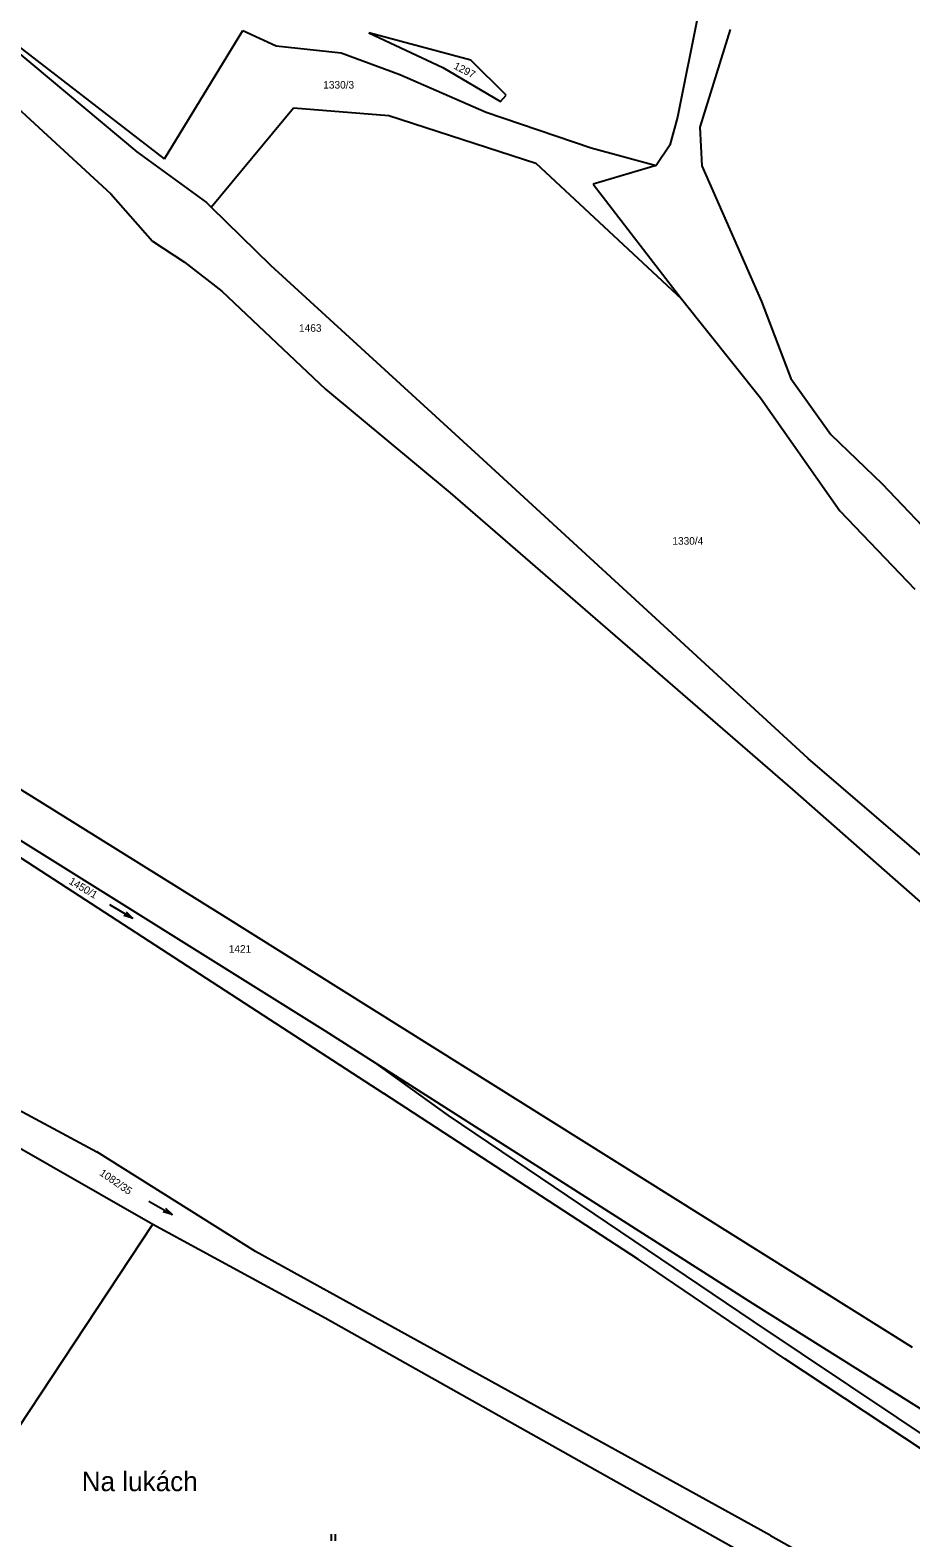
# Model space of a CAD drawing. Extents: x -852001 to -842497, y -1063614 to -1052182.
# Drawn here: x -849610.9 to -849412.3, y -1056094.9 to -1055755 of the extents above; entities that cross this region are included whole.
import ezdxf

# ---------------------------------------------------------------- set-up
doc = ezdxf.new("R2010")
doc.units = 0
for name, color, linetype in [('Default', 7, 'Continuous'), ('KN_HRANICE', 7, 'Continuous'), ('KN_KULTURY', 7, 'Continuous'), ('KN_PARCELY', 7, 'Continuous')]:
    doc.layers.add(name, color=color, linetype=linetype)

# ---------------------------------------------------------------- blocks, each defined once
blk = doc.blocks.new('306')
at = {"layer": 'Default'}
for p, q in [((-0.5, 1.5), (-0.5, 0)), ((0.5, 0), (0.5, 1.5))]:
    blk.add_line(p, q, dxfattribs=at)
blk = doc.blocks.new('802')
at = {"layer": 'Default'}
blk.add_line((-3, 0), (3, 0), dxfattribs=at)
blk.add_lwpolyline([(1, 0.5), (3, 0), (1, -0.5)], dxfattribs=at)

msp = doc.modelspace()

# ---------------------------------------------------------------- linework, layer by layer
at = {"layer": 'KN_HRANICE'}
for p, q in [((-849648.98, -1055740.17), (-849592.74, -1055791.88)), ((-849648.98, -1055740.17), (-849592.74, -1055791.88)), ((-849580.61, -1055784.02), (-849638.69, -1055739.15)), ((-849638.69, -1055739.15), (-849586.87, -1055782.4)), ((-849580.61, -1055784.02), (-849638.69, -1055739.15)), ((-849638.69, -1055739.15), (-849586.87, -1055782.4)), ((-849460.21, -1055751.02), (-849464.92, -1055774.59)), ((-849460.21, -1055751.02), (-849464.92, -1055774.59)), ((-849580.61, -1055784.02), (-849562.93, -1055755.11)), ((-849580.61, -1055784.02), (-849562.93, -1055755.11)), ((-849562.93, -1055755.11), (-849555.45, -1055758.51)), ((-849562.93, -1055755.11), (-849555.45, -1055758.51)), ((-849534.51, -1055755.58), (-849517.87, -1055763.4)), ((-849511.56, -1055761.79), (-849534.51, -1055755.58)), ((-849534.51, -1055755.58), (-849517.87, -1055763.4)), ((-849511.56, -1055761.79), (-849534.51, -1055755.58)), ((-849453.07, -1055754.88), (-849459.95, -1055776.85)), ((-849453.07, -1055754.88), (-849459.95, -1055776.85)), ((-849555.45, -1055758.51), (-849540.76, -1055760.08)), ((-849555.45, -1055758.51), (-849540.76, -1055760.08)), ((-849540.76, -1055760.08), (-849527.52, -1055764.96)), ((-849540.76, -1055760.08), (-849527.52, -1055764.96)), ((-849517.87, -1055763.4), (-849504.83, -1055771.1)), ((-849517.87, -1055763.4), (-849504.83, -1055771.1)), ((-849503.58, -1055769.69), (-849511.56, -1055761.79)), ((-849503.58, -1055769.69), (-849511.56, -1055761.79)), ((-849527.52, -1055764.96), (-849508.07, -1055773.48)), ((-849527.52, -1055764.96), (-849508.07, -1055773.48)), ((-849504.83, -1055771.1), (-849503.58, -1055769.69)), ((-849504.83, -1055771.1), (-849503.58, -1055769.69)), ((-849570.07, -1055794.9), (-849551.55, -1055772.52)), ((-849570.07, -1055794.9), (-849551.55, -1055772.52)), ((-849551.55, -1055772.52), (-849530, -1055774.25)), ((-849551.55, -1055772.52), (-849530, -1055774.25)), ((-849530, -1055774.25), (-849496.9, -1055784.95)), ((-849530, -1055774.25), (-849496.9, -1055784.95)), ((-849508.07, -1055773.48), (-849484.38, -1055781.49)), ((-849508.07, -1055773.48), (-849484.38, -1055781.49)), ((-849464.92, -1055774.59), (-849466.71, -1055780.89)), ((-849464.92, -1055774.59), (-849466.71, -1055780.89)), ((-849459.95, -1055776.85), (-849459.46, -1055785.61)), ((-849459.95, -1055776.85), (-849459.46, -1055785.61)), ((-849484.38, -1055781.49), (-849469.74, -1055785.5)), ((-849484.38, -1055781.49), (-849469.74, -1055785.5)), ((-849466.71, -1055780.89), (-849469.74, -1055785.5)), ((-849466.71, -1055780.89), (-849469.74, -1055785.5)), ((-849586.87, -1055782.4), (-849571.11, -1055793.89)), ((-849586.87, -1055782.4), (-849571.11, -1055793.89)), ((-849496.9, -1055784.95), (-849464.02, -1055815.6)), ((-849496.9, -1055784.95), (-849464.02, -1055815.6)), ((-849469.74, -1055785.5), (-849483.95, -1055789.72)), ((-849469.74, -1055785.5), (-849483.95, -1055789.72)), ((-849459.46, -1055785.61), (-849445.98, -1055816.21)), ((-849459.46, -1055785.61), (-849445.98, -1055816.21)), ((-849592.74, -1055791.88), (-849583.31, -1055802.6)), ((-849592.74, -1055791.88), (-849583.31, -1055802.6)), ((-849483.95, -1055789.72), (-849464.02, -1055815.6)), ((-849483.95, -1055789.72), (-849464.02, -1055815.6)), ((-849571.11, -1055793.89), (-849570.07, -1055794.9)), ((-849571.11, -1055793.89), (-849570.07, -1055794.9)), ((-849570.07, -1055794.9), (-849556.69, -1055807.96)), ((-849570.07, -1055794.9), (-849556.69, -1055807.96)), ((-849583.31, -1055802.6), (-849576.09, -1055807.27)), ((-849583.31, -1055802.6), (-849576.09, -1055807.27)), ((-849576.09, -1055807.27), (-849567.69, -1055813.82)), ((-849576.09, -1055807.27), (-849567.69, -1055813.82)), ((-849556.69, -1055807.96), (-849510.63, -1055850.15)), ((-849556.69, -1055807.96), (-849510.63, -1055850.15)), ((-849567.69, -1055813.82), (-849544.29, -1055835.94)), ((-849567.69, -1055813.82), (-849544.29, -1055835.94)), ((-849464.02, -1055815.6), (-849446.27, -1055837.88)), ((-849464.02, -1055815.6), (-849446.27, -1055837.88)), ((-849445.98, -1055816.21), (-849439.41, -1055833.57)), ((-849445.98, -1055816.21), (-849439.41, -1055833.57)), ((-849544.29, -1055835.94), (-849516.22, -1055859.35)), ((-849544.29, -1055835.94), (-849516.22, -1055859.35)), ((-849439.41, -1055833.57), (-849430.4, -1055846.13)), ((-849439.41, -1055833.57), (-849430.4, -1055846.13)), ((-849446.27, -1055837.88), (-849428.32, -1055863.36)), ((-849446.27, -1055837.88), (-849428.32, -1055863.36)), ((-849430.4, -1055846.13), (-849418.81, -1055857.28)), ((-849430.4, -1055846.13), (-849418.81, -1055857.28)), ((-849435.47, -1055919.24), (-849510.63, -1055850.15)), ((-849435.47, -1055919.24), (-849510.63, -1055850.15)), ((-849723.4, -1055857.46), (-849567.55, -1055954.51)), ((-849723.4, -1055857.46), (-849567.55, -1055954.51)), ((-849516.22, -1055859.35), (-849439.03, -1055926.18)), ((-849516.22, -1055859.35), (-849439.03, -1055926.18)), ((-849418.81, -1055857.28), (-849405.22, -1055871.56)), ((-849418.81, -1055857.28), (-849405.22, -1055871.56)), ((-849428.32, -1055863.36), (-849411.46, -1055881.02)), ((-849428.32, -1055863.36), (-849411.46, -1055881.02)), ((-849670.35, -1055901.85), (-849544.39, -1055980.59)), ((-849670.35, -1055901.85), (-849544.39, -1055980.59)), ((-849412.64, -1055938.82), (-849435.47, -1055919.24)), ((-849412.64, -1055938.82), (-849435.47, -1055919.24)), ((-849439.03, -1055926.18), (-849377.32, -1055980.55)), ((-849439.03, -1055926.18), (-849377.32, -1055980.55)), ((-849625.96, -1055933.24), (-849531.18, -1055994.73)), ((-849625.96, -1055933.24), (-849531.18, -1055994.73)), ((-849372.97, -1055973.13), (-849412.64, -1055938.82)), ((-849372.97, -1055973.13), (-849412.64, -1055938.82)), ((-849567.55, -1055954.51), (-849412.04, -1056051.96)), ((-849567.55, -1055954.51), (-849412.04, -1056051.96)), ((-849544.39, -1055980.59), (-849533.77, -1055987.36)), ((-849544.39, -1055980.59), (-849533.77, -1055987.36)), ((-849642.19, -1055983.02), (-849595.86, -1056007.92)), ((-849642.19, -1055983.02), (-849595.86, -1056007.92)), ((-849645.25, -1055988.73), (-849583.23, -1056024.23)), ((-849645.25, -1055988.73), (-849583.23, -1056024.23)), ((-849533.77, -1055987.36), (-849447.97, -1056042.09)), ((-849533.77, -1055987.36), (-849516.66, -1055999.69)), ((-849533.77, -1055987.36), (-849447.97, -1056042.09)), ((-849533.77, -1055987.36), (-849516.66, -1055999.69)), ((-849473.77, -1056032.19), (-849531.18, -1055994.73)), ((-849473.77, -1056032.19), (-849531.18, -1055994.73)), ((-849516.66, -1055999.69), (-849447.99, -1056046.05)), ((-849516.66, -1055999.69), (-849447.99, -1056046.05)), ((-849560.1, -1056030.34), (-849595.86, -1056007.92)), ((-849560.1, -1056030.34), (-849595.86, -1056007.92)), ((-849629.86, -1056094.78), (-849583.23, -1056024.23)), ((-849629.86, -1056094.78), (-849583.23, -1056024.23)), ((-849583.23, -1056024.23), (-849544.37, -1056045.31)), ((-849583.23, -1056024.23), (-849544.37, -1056045.31)), ((-849443.99, -1056094.41), (-849560.1, -1056030.34)), ((-849443.99, -1056094.41), (-849560.1, -1056030.34)), ((-849440.78, -1056054.56), (-849473.77, -1056032.19)), ((-849440.78, -1056054.56), (-849473.77, -1056032.19)), ((-849447.97, -1056042.09), (-849309.42, -1056129.11)), ((-849447.97, -1056042.09), (-849309.42, -1056129.11)), ((-849544.37, -1056045.31), (-849445.63, -1056100.85)), ((-849544.37, -1056045.31), (-849445.63, -1056100.85)), ((-849447.99, -1056046.05), (-849400.8, -1056077.65)), ((-849447.99, -1056046.05), (-849400.8, -1056077.65)), ((-849379.78, -1056094.91), (-849440.78, -1056054.56)), ((-849379.78, -1056094.91), (-849440.78, -1056054.56)), ((-849443.99, -1056094.41), (-849418.2, -1056108.82)), ((-849443.99, -1056094.41), (-849418.2, -1056108.82))]:
    msp.add_line(p, q, dxfattribs=at)

# ---------------------------------------------------------------- block references
at = {"layer": 'KN_KULTURY'}
for p, rotation in [((-849590.4, -1055953.67), -30.434675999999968), ((-849590.4, -1055953.67), -30.434675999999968), ((-849581.52, -1056020.52), -29.346056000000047), ((-849581.52, -1056020.52), -29.346056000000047)]:
    msp.add_blockref('802', p, dxfattribs=dict(at, rotation=rotation))
msp.add_blockref('306', (-849542.54, -1056095.59), dxfattribs=at)
msp.add_blockref('306', (-849542.54, -1056095.59), dxfattribs=at)

# ---------------------------------------------------------------- texts
at = {"layer": 'KN_PARCELY'}
for s, rotation, p in [('1297', 332.888, (-849515.57, -1055763.61)), ('1297', 332.888, (-849515.57, -1055763.61)), ('1450/1', 329.508, (-849602.34, -1055947.35)), ('1450/1', 329.508, (-849602.34, -1055947.35)), ('1082/35', 325.44, (-849595.41, -1056013.02)), ('1082/35', 325.44, (-849595.41, -1056013.02))]:
    msp.add_text(s, height=1.7, rotation=rotation, dxfattribs=at).set_placement(p)
for s, height, p in [('1330/3', 1.7, (-849544.81, -1055768.17)), ('1330/3', 1.7, (-849544.81, -1055768.17)), ('1463', 1.7, (-849550.27, -1055823)), ('1463', 1.7, (-849550.27, -1055823)), ('1330/4', 1.7, (-849466.1, -1055871)), ('1330/4', 1.7, (-849466.1, -1055871)), ('1421', 1.7, (-849566.12, -1055963)), ('1421', 1.7, (-849566.12, -1055963)), ('Na lukách', 4.4, (-849599.27, -1056084.4)), ('Na lukách', 4.4, (-849599.27, -1056084.4))]:
    msp.add_text(s, height=height, dxfattribs=at).set_placement(p)

doc.saveas('drawing.dxf')
